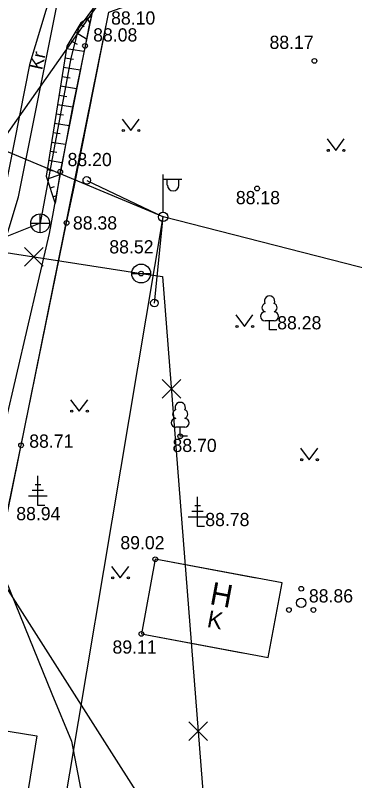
# Model space of a CAD drawing. Extents: x 648748 to 649126, y 6457789 to 6458252.
# Drawn here: x 648958.94 to 648976.94, y 6457996.94 to 6458037.5 of the extents above; entities that cross this region are included whole.
import ezdxf

# ---------------------------------------------------------------- set-up
doc = ezdxf.new("R2010")
doc.units = 0
for name, color, linetype in [('AED', 7, 'Continuous'), ('HALJASTUS', 7, 'Continuous'), ('HOONE', 7, 'Continuous'), ('KORGUS-EH2000', 7, 'Continuous'), ('MPOHULIIN', 7, 'Continuous'), ('PIIR', 7, 'Continuous'), ('POST', 7, 'Continuous'), ('PUU', 7, 'Continuous'), ('RELJEEF', 7, 'Continuous'), ('SITRASS', 7, 'Continuous'), ('SKKAEV', 7, 'Continuous'), ('SKTRASS', 7, 'Continuous'), ('TEE', 7, 'Continuous'), ('VKAEV', 7, 'Continuous'), ('VTRASS', 7, 'Continuous')]:
    doc.layers.add(name, color=color, linetype=linetype)

msp = doc.modelspace()

# ---------------------------------------------------------------- linework, layer by layer
at = {"layer": 'AED'}
msp.add_lwpolyline([(648957.905, 6458010.945), (648958.505, 6458011.137), (648959.247, 6458014.712), (648961.658, 6458026.499), (648962.069, 6458028.393), (648963.906, 6458037.666), (648968.07, 6458039.149)], dxfattribs=at)
at = {"layer": 'HALJASTUS'}
for p, q in [((648964.605, 6458031.999), (648965.068, 6458031.392)), ((648965.068, 6458031.392), (648965.514, 6458031.999)), ((648975.476, 6458030.947), (648975.939, 6458030.34)), ((648975.939, 6458030.34), (648976.385, 6458030.947)), ((648970.636, 6458021.618), (648971.1, 6458021.012)), ((648971.1, 6458021.012), (648971.545, 6458021.618)), ((648961.869, 6458017.13), (648962.333, 6458016.523)), ((648962.333, 6458016.523), (648962.778, 6458017.13)), ((648974.067, 6458014.556), (648974.531, 6458013.95)), ((648974.531, 6458013.95), (648974.976, 6458014.556)), ((648964.043, 6458008.292), (648964.507, 6458007.686)), ((648964.507, 6458007.686), (648964.952, 6458008.292))]:
    msp.add_line(p, q, dxfattribs=at)
for centre in [(648964.667, 6458031.392), (648965.496, 6458031.392), (648975.538, 6458030.34), (648976.367, 6458030.34), (648970.699, 6458021.012), (648971.528, 6458021.012), (648961.932, 6458016.523), (648962.761, 6458016.523), (648974.13, 6458013.95), (648974.959, 6458013.95), (648964.106, 6458007.686), (648964.935, 6458007.686)]:
    msp.add_circle(centre, 0.055, dxfattribs=at)
at = {"layer": 'HOONE'}
for points in [[(648971.719, 6458007.677), (648966.362, 6458008.676), (648965.625, 6458004.723), (648970.982, 6458003.724)], [(648966.362, 6458008.676), (648965.625, 6458004.723), (648972.354, 6458003.468), (648973.09, 6458007.421), (648966.362, 6458008.676)], [(648955.058, 6458000.133), (648960.085, 6457999.314), (648958.123, 6457987.27), (648953.096, 6457988.089), (648955.058, 6458000.133)]]:
    msp.add_lwpolyline(points, dxfattribs=at)
at = {"layer": 'KORGUS-EH2000'}
for centre in [(648962.636, 6458035.873), (648974.807, 6458035.081), (648961.321, 6458029.203), (648971.766, 6458028.32), (648961.658, 6458026.499), (648965.614, 6458023.815), (648967.685, 6458015.193), (648959.247, 6458014.712), (648966.362, 6458008.676), (648965.625, 6458004.723)]:
    msp.add_circle(centre, 0.125, dxfattribs=at)
at = {"layer": 'MPOHULIIN'}
msp.add_line((649008.42, 6458016.198), (648966.776, 6458026.817), dxfattribs=at)
msp.add_lwpolyline([(648951.387, 6457937.05), (648959.585, 6457983.976), (648966.776, 6458026.817), (648933.863, 6458040.57)], dxfattribs=at)
at = {"layer": 'PIIR'}
msp.add_line((648963.88, 6458037.67), (648958.51, 6458011.14), dxfattribs=at)
at = {"layer": 'POST'}
for p, q in [((648966.776, 6458027.067), (648966.776, 6458029.067)), ((648966.776, 6458028.817), (648967.776, 6458028.817)), ((648967.002, 6458028.496), (648967.002, 6458028.817)), ((648967.615, 6458028.496), (648967.615, 6458028.817))]:
    msp.add_line(p, q, dxfattribs=at)
for points in [[(648962.73, 6458028.748), (648966.776, 6458026.817)], [(648966.316, 6458022.25), (648966.776, 6458026.817)]]:
    msp.add_lwpolyline(points, dxfattribs=at)
for centre, radius in [((648962.73, 6458028.748), 0.2), ((648966.776, 6458026.817), 0.25), ((648966.776, 6458026.817), 0.0234), ((648966.316, 6458022.25), 0.2)]:
    msp.add_circle(centre, radius, dxfattribs=at)
msp.add_arc((648967.309, 6458028.496), 0.306, 180, 0, dxfattribs=at)
at = {"layer": 'PUU'}
for p, q in [((648972.663, 6458021.309), (648972.183, 6458021.309)), ((648972.423, 6458020.834), (648972.423, 6458021.309)), ((648972.803, 6458020.834), (648972.423, 6458020.834)), ((648967.925, 6458015.668), (648967.445, 6458015.668)), ((648967.685, 6458015.193), (648967.685, 6458015.668)), ((648968.065, 6458015.193), (648967.685, 6458015.193)), ((648960.137, 6458011.522), (648960.137, 6458013.097)), ((648960.287, 6458012.622), (648959.987, 6458012.622)), ((648960.637, 6458012.022), (648959.637, 6458012.022)), ((648960.437, 6458012.322), (648959.837, 6458012.322)), ((648968.607, 6458010.408), (648968.607, 6458011.983)), ((648960.497, 6458011.522), (648960.137, 6458011.522)), ((648968.907, 6458011.208), (648968.307, 6458011.208)), ((648968.757, 6458011.508), (648968.457, 6458011.508)), ((648969.107, 6458010.908), (648968.107, 6458010.908)), ((648968.967, 6458010.408), (648968.607, 6458010.408))]:
    msp.add_line(p, q, dxfattribs=at)
for centre, radius in [((648974.103, 6458007.113), 0.125), ((648974.103, 6458006.363), 0.25), ((648973.453, 6458005.988), 0.125), ((648974.753, 6458005.988), 0.125)]:
    msp.add_circle(centre, radius, dxfattribs=at)
for centre, radius, start, end in [((648972.423, 6458022.354), 0.277, 332.58, 207.42), ((648972.253, 6458022.007), 0.233, 109.022, 253.142), ((648972.593, 6458022.007), 0.233, 286.851, 70.986), ((648972.185, 6458021.547), 0.238, 90.002, 269.395), ((648972.66, 6458021.547), 0.238, 270.605, 89.998), ((648967.685, 6458016.713), 0.277, 332.58, 207.42), ((648967.515, 6458016.365), 0.233, 109.022, 253.142), ((648967.855, 6458016.365), 0.233, 286.851, 70.986), ((648967.447, 6458015.905), 0.238, 90.002, 269.395), ((648967.922, 6458015.905), 0.238, 270.605, 89.998)]:
    msp.add_arc(centre, radius, start, end, dxfattribs=at)
at = {"layer": 'RELJEEF'}
for p, q in [((648962.892, 6458037.118), (648962.765, 6458037.321)), ((648962.592, 6458036.894), (648962.37, 6458037.026)), ((648962.71, 6458036.241), (648962.114, 6458036.597)), ((648962.232, 6458035.944), (648961.857, 6458036.168)), ((648962.576, 6458035.571), (648961.654, 6458035.719)), ((648962.027, 6458035.153), (648961.575, 6458035.226)), ((648962.383, 6458034.589), (648961.495, 6458034.732)), ((648961.851, 6458034.168), (648961.416, 6458034.238)), ((648962.189, 6458033.608), (648961.336, 6458033.745)), ((648961.675, 6458033.184), (648961.257, 6458033.251)), ((648961.996, 6458032.626), (648961.178, 6458032.758)), ((648961.498, 6458032.199), (648961.098, 6458032.264)), ((648961.802, 6458031.644), (648961.019, 6458031.77)), ((648961.322, 6458031.215), (648960.939, 6458031.277)), ((648960.86, 6458030.783), (648961.608, 6458030.662)), ((648961.146, 6458030.23), (648960.78, 6458030.289)), ((648961.415, 6458029.681), (648960.701, 6458029.796)), ((648960.97, 6458029.246), (648960.621, 6458029.302)), ((648961.294, 6458029.039), (648960.622, 6458028.815)), ((648960.992, 6458028.411), (648960.78, 6458028.341)), ((648961.114, 6458027.925), (648960.938, 6458027.866))]:
    msp.add_line(p, q, dxfattribs=at)
for points in [[(648962.976, 6458037.454), (648962.415, 6458037.102), (648961.678, 6458035.869), (648960.569, 6458028.975), (648961.051, 6458027.53)], [(648962.976, 6458037.454), (648962.858, 6458036.982), (648962.636, 6458035.873), (648961.321, 6458029.203), (648961.051, 6458027.53)]]:
    msp.add_lwpolyline(points, dxfattribs=at)
at = {"layer": 'SITRASS'}
msp.add_lwpolyline([(648966.11, 6458089.841), (648964.318, 6458080.667), (648962.235, 6458070.833), (648961.742, 6458067.306), (648960.68, 6458062.734), (648960.081, 6458059.549), (648958.829, 6458053.903), (648959.436, 6458052.488), (648962.102, 6458051.731), (648964.818, 6458051.004), (648965.35, 6458050.106), (648964.898, 6458046.706), (648961.929, 6458032.449), (648960.742, 6458025.938), (648957.809, 6458013.402), (648957.321, 6458010.707), (648957.473, 6458009.892), (648960.884, 6458001.538), (648961.927, 6457999.033), (648963.394, 6457991.382), (648965.2, 6457986.983), (648965.946, 6457985.459)], dxfattribs=at)
at = {"layer": 'SKKAEV'}
for p, q in [((648960.26, 6458025.978), (648960.26, 6458026.978)), ((648959.76, 6458026.478), (648960.76, 6458026.478))]:
    msp.add_line(p, q, dxfattribs=at)
msp.add_circle((648960.26, 6458026.478), 0.5, dxfattribs=at)
at = {"layer": 'SKTRASS'}
for points in [[(648966.391, 6458041.31), (648963.965, 6458039.119), (648962.283, 6458036.808), (648961.881, 6458035.234), (648960.26, 6458026.478)], [(648960.26, 6458026.478), (648954.414, 6458024.157), (648947.417, 6458021.076)]]:
    msp.add_lwpolyline(points, dxfattribs=at)
at = {"layer": 'TEE'}
for points in [[(648949.689, 6457988.093), (648949.022, 6457989.19), (648951.214, 6457999.425), (648953.382, 6458008.934), (648954.806, 6458015.908), (648958.354, 6458027.992), (648959.727, 6458034.967), (648961.147, 6458039.663), (648962.725, 6458047.115), (648963.962, 6458052.11), (648965.802, 6458054.388), (648967.969, 6458055.624), (648969.67, 6458055.74), (648971.091, 6458054.761), (648978.388, 6458045.705), (649000.128, 6458020.255), (649018.273, 6457999), (649024.176, 6457993.684), (649043.03, 6457975.251)], [(648953.382, 6458008.934), (648959.109, 6458027.881), (648961.591, 6458040.215)]]:
    msp.add_lwpolyline(points, dxfattribs=at)
at = {"layer": 'VKAEV'}
msp.add_line((648965.114, 6458023.815), (648966.114, 6458023.815), dxfattribs=at)
msp.add_circle((648965.614, 6458023.815), 0.5, dxfattribs=at)
at = {"layer": 'VTRASS'}
for p, q in [((648954.479, 6458025.55), (648965.614, 6458023.815)), ((648959.424, 6458025.197), (648960.414, 6458024.207)), ((648959.424, 6458024.207), (648960.414, 6458025.197)), ((648966.722, 6458018.204), (648967.712, 6458017.214)), ((648966.722, 6458017.214), (648967.712, 6458018.204)), ((648968.138, 6458000.054), (648969.128, 6457999.064)), ((648968.138, 6457999.064), (648969.128, 6458000.054))]:
    msp.add_line(p, q, dxfattribs=at)
for points in [[(648954.479, 6458025.55), (648956.102, 6458027.829), (648982.087, 6458064.694)], [(648953.015, 6458024.876), (648956.157, 6458010.76), (648969.796, 6457989.383)], [(648965.614, 6458023.815), (648966.754, 6458023.656), (648969.214, 6457992.111)]]:
    msp.add_lwpolyline(points, dxfattribs=at)

# ---------------------------------------------------------------- texts
at = {"layer": 'HOONE'}
for s, height, p in [('H', 1.2, (648969.201, 6458006.307)), ('K', 0.9, (648969.066, 6458005.096))]:
    msp.add_text(s, height=height, rotation=349.4404, dxfattribs=at).set_placement(p)
at = {"layer": 'KORGUS-EH2000'}
for s, p in [('88.10', (648964.019, 6458037.005)), ('88.08', (648963.068, 6458036.108)), ('88.17', (648972.422, 6458035.716)), ('88.20', (648961.712, 6458029.504)), ('88.18', (648970.636, 6458027.487)), ('88.38', (648961.996, 6458026.146)), ('88.52', (648963.926, 6458024.88)), ('88.28', (648972.83, 6458020.857)), ('88.71', (648959.678, 6458014.586)), ('88.70', (648967.275, 6458014.359)), ('88.94', (648958.99, 6458010.744)), ('88.78', (648969.014, 6458010.431)), ('89.02', (648964.511, 6458009.204)), ('88.86', (648974.51, 6458006.386)), ('89.11', (648964.094, 6458003.676))]:
    msp.add_text(s, height=0.7, dxfattribs=at).set_placement(p)
at = {"layer": 'TEE'}
msp.add_text('Kr', height=0.7, rotation=77.4029, dxfattribs=at).set_placement((648960.36, 6458034.57))

doc.saveas('drawing.dxf')
